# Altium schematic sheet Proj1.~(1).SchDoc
size A4
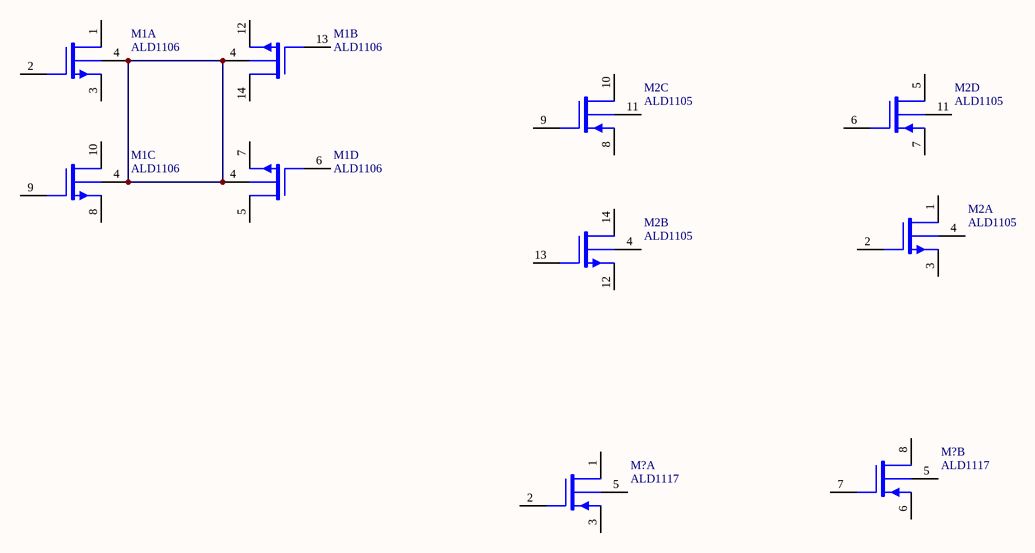
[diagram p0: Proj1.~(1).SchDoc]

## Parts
(Parts that share a designator on the sheet are numbered #1, #2 ... from top to bottom, then left to right.)
M1  ALD1106  [DIP-14]  (parts A,B,C,D of 4)
M2  ALD1105  [DIP-14]  (parts A,B,C,D of 4)
M?#1  ALD1117  [DIP-8]  (part B of 2)
M?#2  ALD1117  [DIP-8]  (part A of 2)

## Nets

Not connected (* = marked no-connect by the designer): M1 1(DN1) 2(GN1) 3(SN1) 4(V-) 5(DN4) 6(GN4) 7(SN4) 8(SN3) 9(GN3) 10(DN3) 12(SN2) 13(GN2) 14(DN2); M2 1(DN1) 2(GN1) 3(SN1) 4(V-) 5(DP1) 6(GP1) 7(SP1) 8(SP2) 9(GP2) 10(DP2) 11(V+) 12(SN2) 13(GN2) 14(DN2); M?#1 5(V+) 6(SP2) 7(GP2) 8(DP2); M?#2 1(DP1) 2(GP1) 3(SP1) 5(V+)

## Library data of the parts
M1 = ALD1106: Quad N-channel matched MOSFET array
M2 = ALD1105: Dual P-channel and dual N-channel matched MOSFET array
M?#1 M?#2 = ALD1117: Dual P-channel matched MOSFET array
